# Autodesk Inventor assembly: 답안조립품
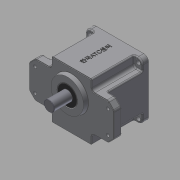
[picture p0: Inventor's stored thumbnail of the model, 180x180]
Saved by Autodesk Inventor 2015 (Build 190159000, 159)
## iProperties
Created: 2016-02
Part Number: 답안조립품
Document SubType Name: Assembly
Designer: Administrator
Author: Administrator
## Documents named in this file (10)
- C:\Users\Administrator\Desktop\460209V1016\답안조립품.iam
- C:\Users\Administrator\Desktop\460209V1016\본체.ipt
- C:\Users\Administrator\Desktop\460209V1016\커버.ipt
- C:\Users\Administrator\Desktop\460209V1016\오일실 8 22 7.ipt
- C:\Users\Administrator\Desktop\460209V1016\베어링 608.ipt
- C:\Users\Administrator\Desktop\460209V1016\메인축.ipt
- C:\Users\Administrator\Desktop\460209V1016\서브축.ipt
- C:\Users\Administrator\Desktop\460209V1016\베어링 6003.ipt
- C:\Users\Administrator\Desktop\460209V1016\오일실 17 32 8.ipt
- C:\Users\Administrator\Desktop\460209V1016\볼트 M4 x 10.ipt
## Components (2 placed, 1 different names)
1. ISO 4762 M4 x 10:1 — Insert:1
2. ISO 4762 M4 x 10:2 — Insert:2
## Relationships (2: Insert 2)
- Insert:1: ISO 4762 M4 x 10:1
- Insert:2: ISO 4762 M4 x 10:2
